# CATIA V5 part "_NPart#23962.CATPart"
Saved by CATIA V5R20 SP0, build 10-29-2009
Part number: DIN6325 Ø3X32
Revision: ANY
Definition: UNKNOWN
Nomenclature: DIN6325 Ø3X32
Source: Unknown
Bounding box of the stored display mesh (mm): x -1.5 to 1.5, y 0 to 32, z -1.5 to 1.5
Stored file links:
  C:\Users\Utente\Desktop\IO LAVORO\3D X SITO CF\CUMSA\3D files AE\AE 062430\_NPart#23962.CATPart
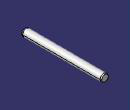
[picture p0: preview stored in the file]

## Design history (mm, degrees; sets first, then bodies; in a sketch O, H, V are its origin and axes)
Body1 "Revolución1" (main body)
  Solid1: solid without history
